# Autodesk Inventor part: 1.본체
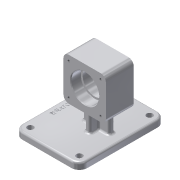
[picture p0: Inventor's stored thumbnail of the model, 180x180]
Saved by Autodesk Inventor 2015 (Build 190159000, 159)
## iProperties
Created: 2020-11
Part Number: 1.본체
Material: 알루미늄 6061
Document SubType Name: Modeling
Designer: pc-04
Density: 2.7 g/cm^3
Appearance: 알루미늄 - 평지
Mass: 683.441 g
Surface Area: 544.674 cm^2
Volume: 253.126 cm^3
Author: pc-04
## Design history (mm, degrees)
sketch "스케치1"
  geometry: L1 (-65, -36)-(65, -36); L2 (65, -36)-(65, 62); L3 (65, 62)-(-65, 62); L4 (-65, 62)-(-65, -36); 1 further point
  constraints: 8 end point, 2 parallel, 1 horizontal, 1 perpendicular
  dimensions: "d0" = 130 distance of L2.end L3.end; "d1" = 98 distance of L1.end L2.end; "d2" = 62 distance from line of point (0, 0) L3; "d3" = 65 distance from line of point (0, 0) L2
extrude "돌출1" new body sketch "스케치1" distance "d4" = 10; taper "d5" = 0 deg
fillet "모깎기1" dims "d6" = 12
sketch "스케치2"
  geometry: L1 (53, -36)-(-53, -36) reference; L2 (-65, -24)-(-65, 50) reference; L3 (-53, 62)-(53, 62) reference; L4 (65, 50)-(65, -24) reference; A1 r 12 centre (53, -24) between (53, -36) and (65, -24) reference; A2 r 12 centre (-53, -24) between (-65, -24) and (-53, -36) reference; A3 r 12 centre (-53, 50) between (-53, 62) and (-65, 50) reference; A4 r 12 centre (53, 50) between (65, 50) and (53, 62) reference; 1 further point
hole "구멍1" sketch "스케치2" at (-53, 50), (-53, -24), (53, -24), (53, 50) diameter "d7" = 9; stored, may be unused: countersink angle "d11" = 90 deg, drill point angle "d13" = 118 deg; dims "d8" = 6, "d9" = 4, "d10" = 2, "d12" = 8
node "작업 평면1"
sketch "스케치3"
  geometry: L1 (21, -32)-(-21, -32); L2 (-21, -32)-(-21, 32); L3 (-21, 32)-(21, 32); L4 (21, 32)-(21, -32); L5 (21, -32)-(-21, 32); L6 (-21, -32)-(21, 32); 1 further point
  constraints: 12 end point, 2 midpoint, 2 parallel, 1 horizontal, 1 perpendicular
  dimensions: "d15" = 42 distance of L2.end L3.end; "d16" = 64 distance of L1.end L2.end
extrude "돌출2" join sketch "스케치3" stored distance "d17" = 64; taper "d18" = 0 deg
sketch "스케치4"
  geometry: L1 (-28, 94)-(-28, -4) reference; L2 (-28, -4)-(-38, -4) reference; L3 (-38, -4)-(-38, 94) reference; L4 (-38, 94)-(-28, 94) reference; L5 (64, 64)-(64, 0) reference; L6 (64, 0)-(0, 0) reference; L7 (0, 0)-(0, 64) reference; L8 (0, 64)-(64, 64) reference; 1 further point
  node "절단 모서리 투영2"
sketch "스케치5"
  geometry: L1 (21, 102)-(21, 38) reference; L2 (21, 70)-(-21, 70); L3 (-21, 38)-(-21, 102) reference; L4 (21, 70)-(6, 70); L5 (6, 70)-(6, 91); L6 (6, 91)-(21, 91); L7 (21, 91)-(21, 70); L8 (6, 70)-(-6, 70); L9 (-6, 70)-(-6, 88); L10 (-6, 88)-(6, 88); L11 (6, 88)-(6, 70); L12 (-6, 70)-(-21, 70); L13 (-21, 70)-(-21, 91); L14 (-21, 91)-(-6, 91); L15 (-6, 91)-(-6, 70); 2 further points
  constraints: 26 end point, 6 parallel, 3 horizontal, 3 midpoint, 3 perpendicular, 2 point on line
  dimensions: "d19" = 15 distance of L5.end L6.end; "d20" = 15 distance of L13.end L14.end; "d21" = 42 diameter of L6 L2; "d22" = 36 diameter of L10 L8
revolve "회전1" sketch "스케치5" stored, may be unused: angle "d23" = 90 deg
fillet "모깎기2" dims "d24" = 8
sketch "스케치7"
  geometry: L1 (-17, 4)-(17, 4); L2 (17, 4)-(17, -4); L3 (17, -4)-(-17, -4); L4 (-17, -4)-(-17, 4); L5 (-4, 20)-(4, 20); L6 (4, 20)-(4, -20); L7 (4, -20)-(-4, -20); L8 (-4, -20)-(-4, 20); 5 further points
  constraints: 16 end point, 4 midpoint, 4 parallel, 2 horizontal, 2 horizontal alignment, 2 perpendicular, 2 vertical alignment
  dimensions: "d25" = 8 distance between parallel lines of L8 L6; "d26" = 8 distance between parallel lines of L3 L1; "d27" = 34 distance between parallel lines of L4 L2; "d28" = 40 distance between parallel lines of L5 L7
extrude "돌출3" join sketch "스케치7" stored distance "d29" = 64; taper "d30" = 0 deg
fillet "모깎기3" dims "d31" = 3
fillet "모깎기4" dims "d32" = 3
fillet "모깎기5" dims "d33" = 0.3
sketch "스케치8"
  geometry: L1 (95, 86)-(102, 86) reference; L2 (102, 86)-(102, -12) reference; L3 (102, -12)-(95, -12) reference; L4 (92, -9)-(92, 83) reference; L5 (64, 48)-(64, 0) reference; L6 (56, -8)-(8, -8) reference; L7 (0, 0)-(0, 48) reference; L8 (8, 56)-(56, 56) reference; C1 r 21 at (32, 24) reference; C2 r 21 at (32, 24) reference; A1 r 3 centre (95, 83) between (95, 86) and (92, 83) reference; A2 r 3 centre (95, -9) between (92, -9) and (95, -12) reference; A3 r 8 centre (56, 0) between (56, -8) and (64, 0) reference; A4 r 8 centre (8, 0) between (0, 0) and (8, -8) reference; A5 r 8 centre (8, 48) between (8, 56) and (0, 48) reference; A6 r 8 centre (56, 48) between (64, 48) and (56, 56) reference; 1 further point
hole "구멍2" sketch "스케치8" at (8, 0), (8, 48), (56, 48), (56, 0) diameter "d34" = 3.242; stored, may be unused: countersink angle "d38" = 90 deg, drill point angle "d40" = 118 deg; dims "d35" = 8, "d36" = 4, "d37" = 2, "d39" = 10
sketch "스케치9"
  geometry: L1 (65, -24)-(65, 50) reference; L2 (53, 62)-(-53, 62) reference; 2 further points
  constraints: 1 other
  dimensions: "d41" = 65 distance from line of point (0, 52) L1; "d42" = 10 distance from line of point (0, 52) L2
feature "엠보싱1" sketch "스케치9" dims "d0" = 130, "d1" = 98, "d2" = 62, "d3" = 65, "d15" = 42, "d16" = 64, "d43" = 0.5, "d44" = 0
chamfer "모따기1" distance "d45" = 1; stored, may be unused: second distance "d46" = 2, angle "d47" = 45 deg
node "솔리드1"
mirror "대칭1"
node "절단 모서리 투영1"
node "절단 모서리 투영4"
